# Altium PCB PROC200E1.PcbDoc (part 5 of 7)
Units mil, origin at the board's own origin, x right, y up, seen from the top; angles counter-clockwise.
Board outline 4163.97 x 3505.34 mil, 6 copper layers (Top Layer, GND1, SIG1, PWR, GND2, Bottom), stack 58.132 mil thick; 367 components, 387 nets, 1784 pads, 858 vias.
Unrouted connection lines stored in the file: 17.
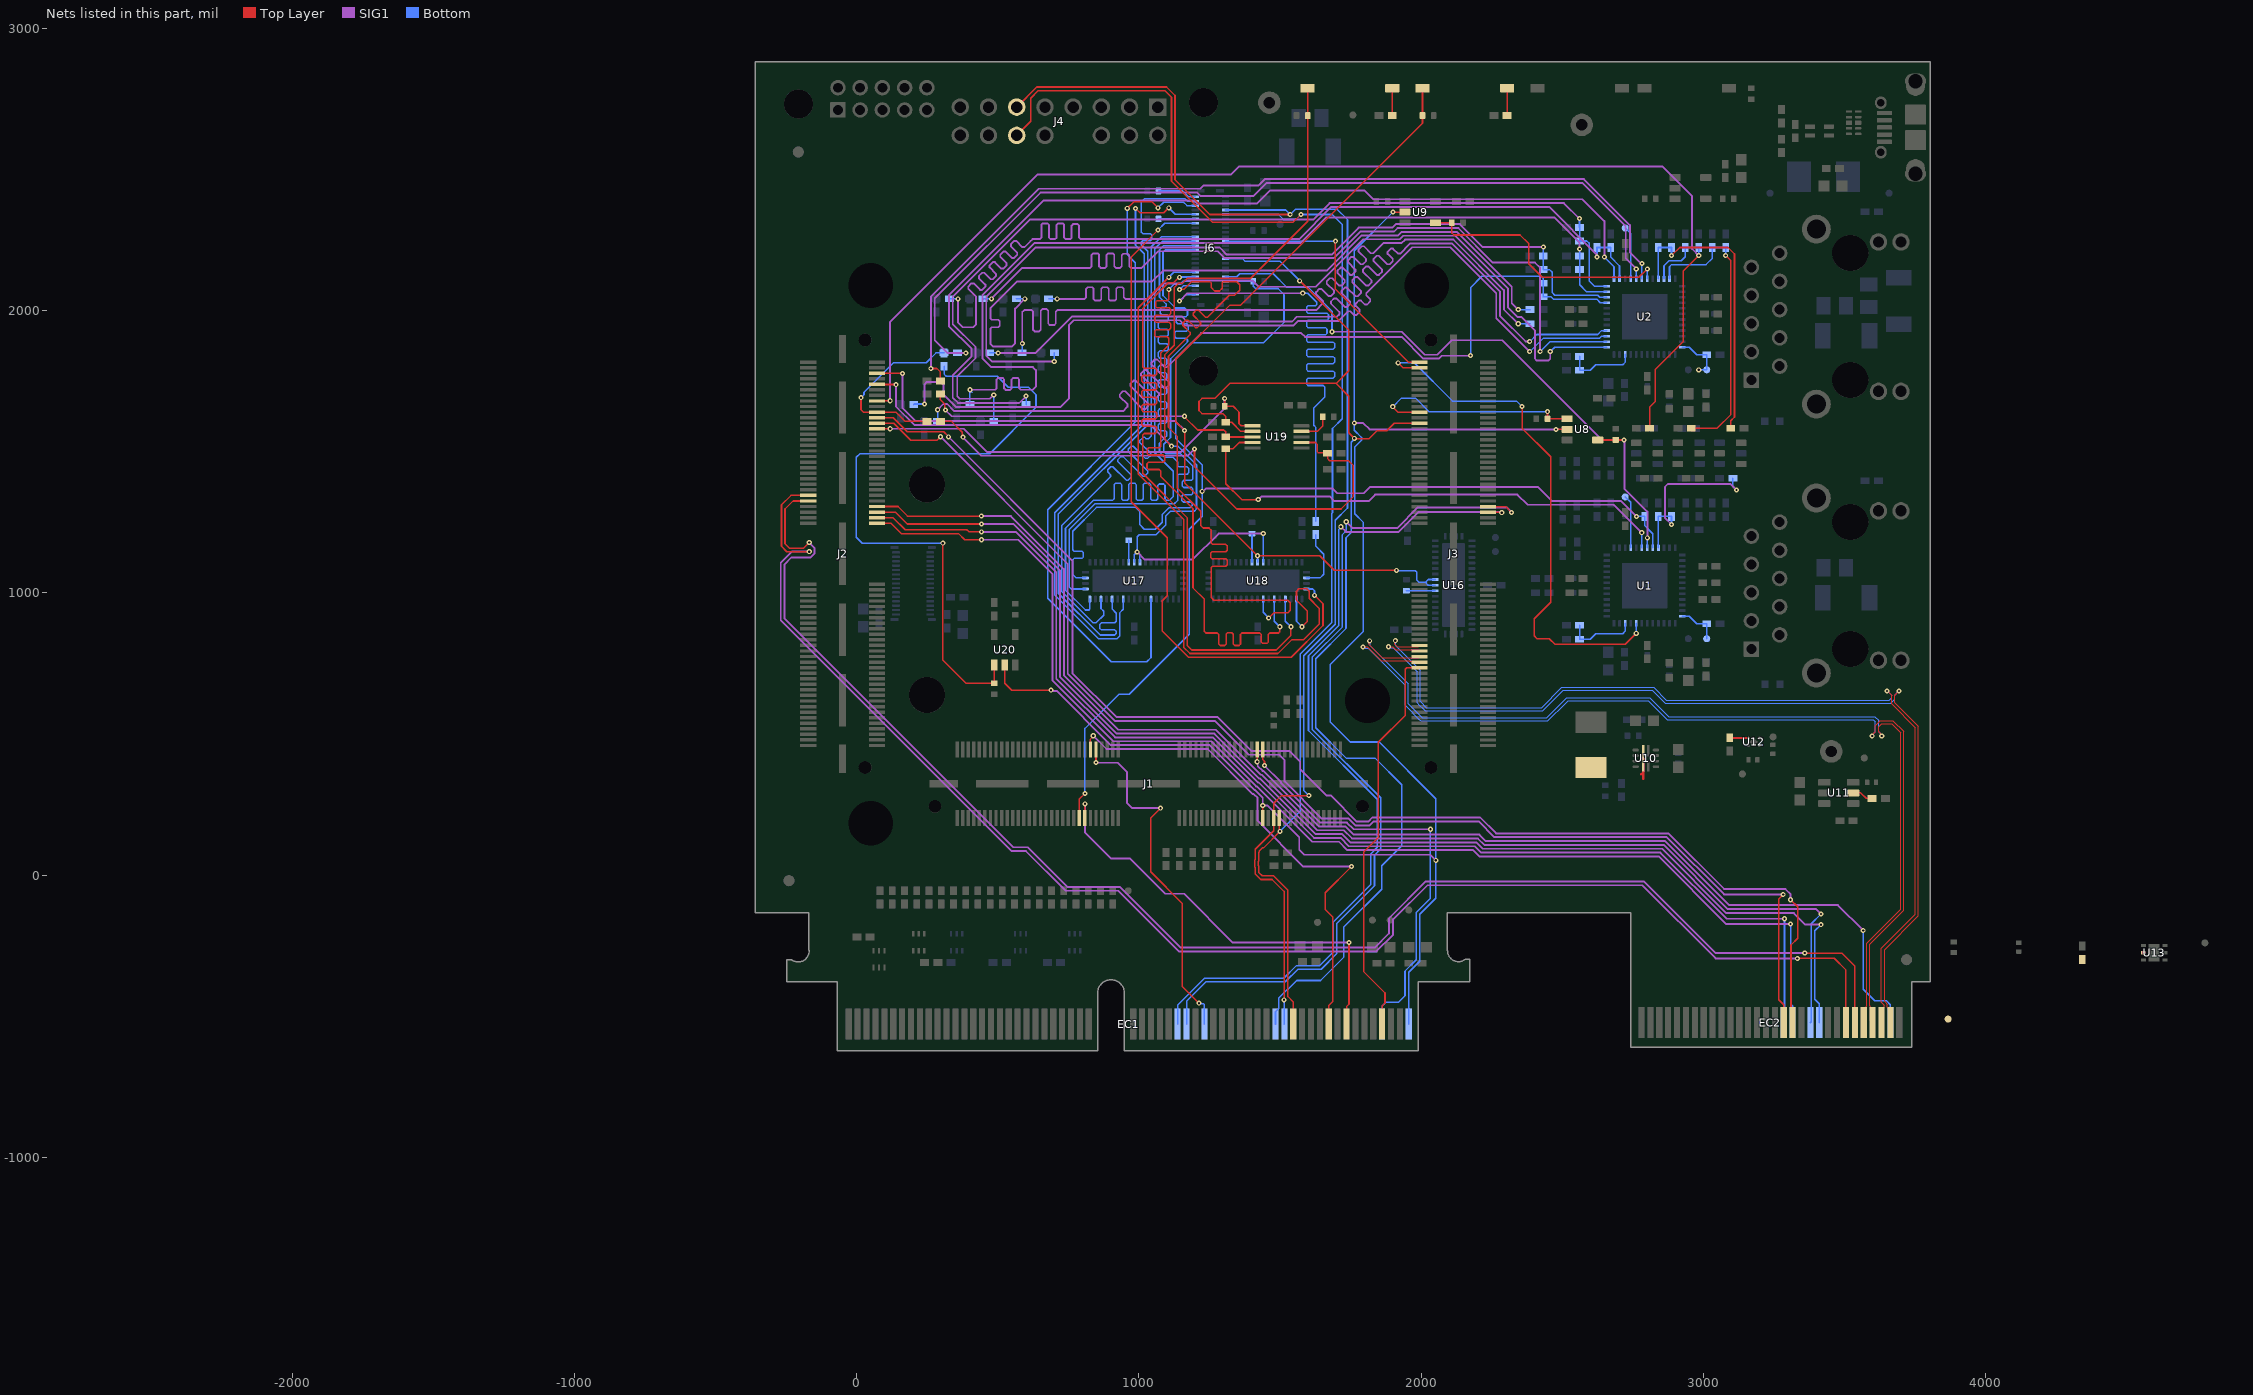
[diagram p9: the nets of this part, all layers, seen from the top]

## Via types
v1: diameter 18, hole 8, Top Layer to Bottom, tented both sides, 729 vias
v2: diameter 19.68, hole 7.87, Top Layer to Bottom, 77 vias
v3: diameter 24, hole 12, Top Layer to Bottom, tented both sides, 52 vias

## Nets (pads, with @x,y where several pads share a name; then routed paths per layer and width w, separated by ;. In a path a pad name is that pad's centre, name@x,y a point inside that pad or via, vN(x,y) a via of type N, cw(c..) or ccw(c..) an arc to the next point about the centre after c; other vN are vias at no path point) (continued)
ICSSM_MII1_RXD0: J6.23 U17.41 | length 2290.4
  Bottom w5.66: U17.41@810.53,1052.88 777.47,1052.88 765.17,1065.18 765.17,1088.34 765.17,1116.83 770.3,1121.96 798.11,1121.96 803.24,1127.1 803.24,1142.49 798.11,1147.62 770.3,1147.62 765.17,1152.76 765.17,1161.3 765.17,1218.03 849.72,1302.59 988.7,1302.59 1002.48,1288.81 1002.48,1241.75 1019.22,1225.01 1057.52,1225.01 1082.58,1250.06 1082.58,1277.88 1106.27,1301.56 1181,1301.56 1186.17,1306.73 1189,1309.57 1189,1316.82 1183.87,1321.95 1156.42,1321.95 1151.29,1327.09 1151.29,1342.48 1156.42,1347.61 1186.21,1347.61 1191.34,1352.75 1191.34,1368.14 1186.21,1373.27 1159.24,1373.27 1154.1,1378.41 1154.1,1393.8 1159.24,1398.93 1186.21,1398.93 1191.34,1404.07 1191.34,1414.21 1191.34,1448.76 1147.1,1493 1097,1493 1088.06,1501.94 1088.06,1526.51 1112,1550.45 1112,1828.89 1172.08,1888.97 1172.08,1893.89 1172.08,1896.72 1166.94,1901.85 1132.55,1901.85 1127.42,1906.99 1127.42,1922.38 1132.55,1927.51 1169.03,1927.51 1174.16,1932.65 1174.16,1948.04 1169.03,1953.17 1137.82,1953.17 1132.69,1958.31 1132.69,1973.7 1137.82,1978.83 1166.94,1978.83 1172.08,1983.97 1172.08,1999.34 1162.27,2009.15 1129.61,2009.15 1085.39,2053.38 1085.39,2206.34 1093.71,2214.65 J6.23@1199.93,2214.65
ICSSM_MII1_RXD1: J6.25 U17.39 | length 2290.4
  Bottom w5.66: U17.39@810.53,1013.51 760.06,1013.51 752.51,1021.06 752.51,1223.28 844.48,1315.25 1125.25,1315.25 1137,1327 1137,1386.93 1137,1415.42 1142.13,1420.55 1170.85,1420.55 1175.98,1425.69 1175.98,1441.08 1170.85,1446.21 1142.13,1446.21 1137,1451.35 1137,1464.34 1130.59,1470.75 1121,1480.34 1091.76,1480.34 1073,1499.1 1073,1530.49 1098,1555.49 1098,1566.93 1098,1569.76 1092.87,1574.89 1074.24,1574.89 1069.1,1580.02 1069.1,1595.42 1074.24,1600.55 1094.21,1600.55 1099.34,1605.68 1099.34,1621.08 1094.21,1626.21 1074.24,1626.21 1069.1,1631.34 1069.1,1646.74 1074.24,1651.87 1094.21,1651.87 1099.34,1657 1099.34,1672.4 1094.21,1677.53 1074.24,1677.53 1069.1,1682.66 1069.1,1698.06 1074.24,1703.19 1094.21,1703.19 1099.34,1708.32 1099.34,1723.72 1094.21,1728.85 1074.24,1728.85 1069.1,1733.98 1069.1,1749.38 1074.24,1754.51 1094.21,1754.51 1099.34,1759.64 1099.34,1775.04 1094.21,1780.17 1074.24,1780.17 1069.1,1785.3 1069.1,1800.7 1074.24,1805.83 1094.21,1805.83 1099.34,1810.96 1099.34,1826.36 1094.21,1831.49 1074.24,1831.49 1069.1,1836.62 1069.1,1852.02 1074.24,1857.15 1099.03,1857.15 1104.16,1862.28 1104.16,1877.68 1099.03,1882.81 1074.24,1882.81 1069.1,1887.94 1069.1,1903.34 1074.24,1908.47 1099.03,1908.47 1104.16,1913.6 1104.16,1929 1099.03,1934.13 1074.24,1934.13 1069.1,1939.26 1069.1,1954.66 1074.24,1959.79 1099.03,1959.79 1104.16,1964.92 1104.16,1980.32 1099.03,1985.45 1080.39,1985.45 1075.26,1990.58 1075.26,2005.98 1080.39,2011.11 1091.1,2011.11 1096.23,2016.24 1096.23,2023.5 1072.73,2047 1072.73,2059.61 1072.73,2215.26 1087.88,2230.4 J6.25@1199.93,2230.4
ICSSM_MII1_RXD2: J6.27 U17.38 | length 2290.4
  Bottom w5.66: U17.38@826.28,978.08 826.28,942.42 822.97,939.1 810.37,939.1 739.85,1009.62 739.85,1228.52 839.93,1328.6 904.94,1328.6 907.78,1328.6 912.91,1333.74 912.91,1383.55 918.04,1388.69 933.44,1388.69 938.57,1383.55 938.57,1333.04 943.7,1327.91 959.1,1327.91 964.23,1333.04 964.23,1383.55 969.36,1388.69 984.76,1388.69 989.89,1383.55 989.89,1333.04 995.02,1327.91 1010.42,1327.91 1015.55,1333.04 1015.55,1383.55 1020.68,1388.69 1036.08,1388.69 1041.21,1383.55 1041.21,1333.04 1046.34,1327.91 1061.74,1327.91 1066.87,1333.04 1066.87,1380.3 1072,1385.43 1087.4,1385.43 1092.53,1380.3 1092.53,1333.74 1097.66,1328.6 1109.14,1328.6 1109.6,1328.6 1122,1341 1122,1430.61 1056.44,1496.16 1056.44,2218.93 1083.67,2246.15 J6.27@1199.93,2246.15
ICSSM_MII1_RXD3: J6.29 U17.36 | length 2290.4
  Bottom w5.66: U17.36@865.65,978.08 865.65,944.59 875.04,935.19 875.04,920.48 849.08,894.52 836.59,894.52 727.19,1003.91 727.19,1239.31 897.3,1409.42 899.3,1411.42 899.3,1418.68 889.36,1428.63 889.36,1435.89 900.24,1446.77 907.5,1446.77 954.89,1399.38 962.15,1399.38 973.04,1410.27 973.04,1417.52 925.65,1464.92 925.65,1472.17 936.53,1483.06 943.79,1483.06 1013.25,1413.6 1020.51,1413.6 1031.4,1424.49 1031.4,1431.74 961.93,1501.21 961.93,1508.46 972.82,1519.35 980.08,1519.35 1023.26,1476.17 1030.52,1476.17 1041.4,1487.06 1041.4,1494.32 1003.16,1532.56 1003.16,1539.81 1014.05,1550.7 1021.31,1550.7 1026.31,1545.69 1033.57,1545.69 1038.39,1550.51 1043.78,1555.9 1043.78,2225.87 1079.81,2261.9 J6.29@1199.93,2261.9
ICSSM_MII1_RXDV: J6.45 U17.34 | length 2290.4
  Bottom w5.66: U17.34@905.02,978.08 905.02,942.53 919.71,927.85 919.86,927.69 919.86,899.35 914.73,894.22 866.99,894.22 861.86,889.09 861.86,873.69 866.99,868.56 914.73,868.56 919.86,863.43 919.86,856.56 919.86,856.37 913.92,850.42 862.59,850.42 714.53,998.48 714.53,1278.96 1031.12,1595.56 1031.12,2210.31 1022.78,2218.65 1008.54,2232.89 1008.54,2242.01 1013.67,2247.14 1040.45,2247.14 1045.58,2252.28 1045.58,2267.67 1040.45,2272.8 1013.67,2272.8 1008.54,2277.94 1008.54,2299.53 1008.54,2385.86 1019.34,2396.66 1163.43,2396.66 1172.2,2387.88 J6.45@1199.93,2387.88
ICSSM_MII1_RXER: J6.39 U17.32 | length 2182.8
  Top Layer w5.66: v1(988,2362) 1003.57,2346.43 1088.06,2346.43 v1(1105.89,2364.26)
  Bottom w5.66: U17.32@944.39,978.08 944.39,941.96 932.57,930.13 932.57,848.03 922.28,837.75 856.58,837.75 701.87,992.46 701.87,1284.21 1018.46,1600.8 1018.46,2201.25 988,2231.71 v1(988,2362) ; v1(1105.89,2364.26) 1128.6,2341.56 1199.01,2341.56 J6.39@1199.93,2340.64
ICSSM_MII1_RXLINK: J6.43 U17.27 | length 2467.7
  Top Layer w5.66: v1(958.67,2362.28) 981.39,2385.01 1047.15,2385.01 v1(1067.89,2364.26)
  Bottom w5.66: v1(958.67,2362.28) 958.67,2198.44 987.34,2169.76 987.34,1605.48 676.55,1294.69 676.55,980.56 901.55,755.56 1027.51,755.56 1042.82,770.87 U17.27@1042.82,978.08 ; v1(1067.89,2364.26) 1087.63,2384 1158.18,2384 1170.05,2372.14 J6.43@1199.93,2372.14
ICSSM_MII1_TXCLK: J6.3 R153.2 | length 2294.8
  SIG1 w6.66: v1(1143.89,2033.94) 1171.62,2061.66 v1(1580.57,2061.66)
  Bottom w5.66: v1(1143.89,2033.94) 1167.13,2057.17 J6.3@1199.93,2057.17 ; v1(1580.57,2061.66) 1597.74,2061.66 1614.19,2045.22 1630.29,2029.11 1630.29,2021.86 1625.16,2016.72 1599.14,2016.72 1594.01,2011.59 1594.01,1996.2 1599.14,1991.06 1666.38,1991.06 1671.51,1985.93 1671.51,1970.54 1666.38,1965.4 1599.14,1965.4 1594.01,1960.27 1594.01,1944.88 1599.14,1939.74 1661.21,1939.74 1666.34,1934.61 1666.34,1919.22 1661.21,1914.08 1599.14,1914.08 1594.01,1908.95 1594.01,1893.56 1599.14,1888.42 1688.02,1888.42 1693.15,1883.29 1693.15,1867.9 1688.02,1862.76 1599.14,1862.76 1594.01,1857.63 1594.01,1842.24 1599.14,1837.1 1688.02,1837.1 1693.15,1831.97 1693.15,1816.58 1688.02,1811.44 1599.14,1811.44 1594.01,1806.31 1594.01,1790.92 1599.14,1785.78 1688.02,1785.78 1693.15,1780.65 1693.15,1765.26 1688.02,1760.12 1599.14,1760.12 1594.01,1754.99 1594.01,1739.6 1599.14,1734.46 1653.03,1734.46 1658.16,1729.33 1658.16,1709.94 1658.16,1693.71 1619.42,1654.97 1619.42,1593.67 1627.09,1586 R153.2@1627.09,1253.39
ICSSM_MII1_TXD0: J6.7 U18.29 | length 2485.3
  Top Layer w5.66: v1(1143.89,2074.96) 1159.09,2074.96 1186.44,2102.31 1252.13,2102.31 1256.76,2097.69 1256.76,2080.76 1267.98,2069.54 1285.54,2069.54 1294.95,2078.95 1294.95,2098.8 1298.27,2102.12 1346.77,2102.12 1356.96,2091.93 1356.96,2072.29 1338.76,2054.09 1320.09,2054.09 1293.76,2027.76 1242.82,1976.82 1235.56,1976.82 1210.63,2001.76 1203.37,2001.76 1192.48,1990.87 1192.48,1983.62 1218.2,1957.9 1218.2,1950.64 1207.31,1939.76 1200.05,1939.76 1173.63,1966.18 1166.38,1966.18 1155.49,1955.29 1155.49,1948.03 1181.13,1922.39 1181.13,1915.13 1179.13,1913.13 1104.72,1838.72 1104.72,1585.98 1135.28,1555.42 1135.28,1372.18 1218.71,1288.74 1218.71,1238.44 1227.38,1229.77 1248.31,1229.77 1255.87,1222.21 1255.87,1193.21 1255.87,1176.73 1261,1171.6 1307.59,1171.6 1312.73,1166.47 1312.73,1151.07 1307.59,1145.94 1259.22,1145.94 1254.09,1140.81 1254.09,1125.41 1259.22,1120.28 1307.59,1120.28 1312.73,1115.15 1312.73,1099.75 1307.59,1094.62 1261,1094.62 1255.87,1089.49 1255.87,1061 1255.87,983.29 1265.16,974 1527.4,974 1536.33,965.08 1536.33,937.92 1528.15,929.74 1478.62,929.74 v1(1459.8,910.92)
  Bottom w5.66: v1(1143.89,2074.96) 1144.7,2074.96 1158.4,2088.67 J6.7@1199.93,2088.67 ; U18.29@1440.11,978.08 1440.11,930.72 1459.8,911.04 v1(1459.8,910.92)
ICSSM_MII1_TXD1: J6.9 U18.27 | length 2484
  Top Layer w5.66: v1(1105.89,2074.96) 1105.89,2059.27 1105.89,2040.39 1100.76,2035.26 1064.01,2035.26 1058.88,2030.13 1058.88,2014.73 1064.01,2009.6 1107.02,2009.6 1112.15,2004.47 1112.15,1989.07 1107.02,1983.94 1061.03,1983.94 1055.89,1978.81 1055.89,1963.41 1061.03,1958.28 1107.02,1958.28 1112.15,1953.15 1112.15,1937.75 1107.02,1932.62 1061.03,1932.62 1055.89,1927.49 1055.89,1912.09 1061.03,1906.96 1100.76,1906.96 1105.89,1901.83 1105.89,1899 1105.89,1878.28 1077.62,1850.01 1077.62,1553.31 1077.62,1519.2 1072.49,1514.07 1034.85,1514.07 1029.72,1508.94 1029.72,1493.54 1034.85,1488.41 1086.21,1488.41 1091.34,1483.28 1091.34,1467.88 1086.21,1462.75 1033.84,1462.75 1028.71,1457.62 1028.71,1442.22 1033.84,1437.09 1072.49,1437.09 1077.62,1431.96 1077.62,1429.13 1077.62,1411.89 1191.74,1297.77 1191.74,1017.34 1231.27,977.81 1231.27,863.63 1237.33,857.57 1249.44,857.57 1277.93,857.57 1283.06,852.44 1283.06,818.64 1288.2,813.51 1303.59,813.51 1308.72,818.64 1308.72,853.38 1313.86,858.51 1329.25,858.51 1334.38,853.38 1334.38,818.64 1339.52,813.51 1354.91,813.51 1360.04,818.64 1360.04,852.44 1365.18,857.57 1384,857.57 1399.52,857.57 1428.01,857.57 1433.14,852.44 1433.14,825.8 1438.27,820.66 1453.67,820.66 1458.8,825.8 1458.8,852.44 1463.93,857.57 1494,857.57 1494.76,857.57 1499.17,861.98 v1(1499.17,879.94)
  Bottom w5.66: v1@1105.89,2077.96 1108.89,2077.96 1123.72,2092.79 1144.5,2092.79 1156.13,2104.42 J6.9@1199.93,2104.42 ; U18.27@1479.48,978.08 1479.48,899.62 v1(1499.17,879.94)
ICSSM_MII1_TXD2: J6.11 U18.25 | length 2485.7
  Top Layer w5.66: v1(1143.89,2117.99) 1142.11,2117.99 1122.4,2098.27 1103.99,2098.27 1013.3,2007.59 1013.3,1890 1013.3,1800.69 1018.43,1795.56 1057.39,1795.56 1062.52,1790.43 1062.52,1775.03 1057.39,1769.9 1015.61,1769.9 1010.48,1764.77 1010.48,1749.37 1015.61,1744.24 1058.17,1744.24 1063.3,1739.11 1063.3,1723.71 1058.17,1718.58 1015.61,1718.58 1010.48,1713.45 1010.48,1698.05 1015.61,1692.92 1058.17,1692.92 1063.3,1687.79 1063.3,1672.39 1058.17,1667.26 1015.61,1667.26 1010.48,1662.13 1010.48,1646.73 1015.61,1641.6 1058.17,1641.6 1063.3,1636.47 1063.3,1621.07 1058.17,1615.94 1015.61,1615.94 1010.48,1610.81 1010.48,1595.41 1015.61,1590.28 1058.17,1590.28 1063.3,1585.15 1063.3,1569.75 1058.17,1564.62 1018.43,1564.62 1013.3,1559.49 1013.3,1531 1013.3,1423.47 1171.73,1265.04 1171.73,812.87 1187.04,797.56 1486.21,797.56 1538.54,849.88 v1(1538.54,879.94)
  Bottom w5.66: v1(1143.89,2117.99) 1144.98,2119.08 1198.84,2119.08 J6.11@1199.93,2120.17 ; U18.25@1518.85,978.08 1518.85,899.62 v1(1538.54,879.94)
ICSSM_MII1_TXD3: J6.13 U18.23 | length 2493.9
  Top Layer w5.66: v1(1105.89,2117.99) 1105.8,2117.99 997.82,2010.01 997.82,1421.05 1159.07,1259.8 1159.07,806.64 1180.81,784.9 1492.52,784.9 1541.99,834.37 1584.23,834.37 1638.27,888.41 1638.27,945.57 1603.2,980.64 1603.2,1005.25 1594.37,1014.07 1566.7,1014.07 1558.17,1005.54 1558.17,974.05 1595.74,936.48 1595.74,897.77 v1(1577.91,879.94)
  Bottom w5.66: v1(1105.89,2117.99) 1123.82,2135.91 J6.13@1199.93,2135.91 ; U18.23@1558.22,978.08 1558.22,899.62 v1(1577.91,879.94)
ICSSM_MII1_TXEN: J6.35 U18.21 | length 2483.3
  Top Layer w5.66: v1(1067.89,2285.52) 972.5,2190.13 972.5,1322.49 1100.23,1194.76 1100.23,989.34 1082.9,972 1082.9,864.49 1175.77,771.63 1539.38,771.63 1652.04,884.28 1652.04,960.96 v1(1622,991)
  Bottom w5.66: v1(1067.89,2285.52) 1091.52,2309.14 J6.35@1199.93,2309.14 ; U18.21@1593.65,1013.51 1616.09,1013.51 1622,1007.6 v1(1622,991)
JTAG_TDO/ETH1_GPIO_1: R67.1 R76.2 U2.22 | length 250
  Bottom w5.66: R67.1@2561.67,1837.3 R76.2@2561.67,1788.19 2599.38,1788.19 2618.87,1807.69 2713.98,1807.69 2722.59,1816.3 U2.22@2722.59,1844.65
JTAG_TDO/PHY2_GPIO_1: R14.1 R23.2 U1.22 | length 250
  Bottom w5.66: R14.1@2561.67,884.54 R23.2@2561.67,835.44 2599.38,835.44 2618.87,854.93 2713.98,854.93 2722.59,863.54 U1.22@2722.59,891.89
LED2_2: R10.1 R19.2 R120.1 U1.45 | length 644.4
  SIG1 w6.66: v1(2887.03,1242.08) 2863.46,1265.64 2863.46,1374.96 2874.6,1386.1 3095.34,1386.1 v1(3116.99,1364.44)
  Bottom w5.66: U1.45@2840.7,1159.61 2840.7,1269.61 R10.1@2839.49,1270.82 R19.2@2887.03,1270.82 v1(2887.03,1242.08) ; R120.1@3104.35,1405.81 3104.35,1377.9 3116.99,1365.25 v1(3116.99,1364.44)
LED_0: R64.1 R73.2 R109.1 U2.47 | length 1053.1
  Top Layer w5.66: R109.1@2956.9,1582.81 3048.18,1582.81 3097.49,1632.13 3097.49,2176.37 v1(3079.03,2194.83)
  Bottom w5.66: U2.47@2880.07,2112.37 2880.07,2155.7 2887.35,2162.98 3009.25,2162.98 3031.24,2184.96 R64.1@3031.24,2223.58 R73.2@3079.03,2223.58 v1(3079.03,2194.83)
LED_2: R65.1 R74.2 R113.1 U2.45 | length 1056
  Top Layer w5.66: v1(2887.03,2194.83) 2915.78,2223.58 3087.42,2223.58 3110.15,2200.85 3110.15,1622.76 3096.87,1609.47 R113.1@3096.87,1582.81
  Bottom w5.66: U2.45@2840.7,2112.37 2840.7,2222.37 R65.1@2839.49,2223.58 R74.2@2887.03,2223.58 v1(2887.03,2194.83)
MCU_GPIO63: EC2.167 J2.50 | length 5382.8
  Top Layer w5.66: J2.50@-171.52,1345.08 -233.15,1345.08 -266.55,1311.68 -266.55,1164.9 -247.65,1146 v1(-168,1146) ; v1(3332.7,-295.23) 3463.62,-295.23 3505.04,-336.65 EC2.167@3505.04,-522.97
  SIG1 w6.66: v1(-168,1146) -229.63,1146 -269.04,1106.59 -269.04,903.01 548.94,85.03 599.9,85.03 740.67,-55.75 926.74,-55.75 1141.79,-270.79 1841.41,-270.79 1899.69,-212.5 1899.69,-158.78 2022.47,-36 2783.84,-36 3043.07,-295.23 v1(3332.7,-295.23)
MCU_GPIO64: EC2.169 J2.52 | length 5406.8
  Top Layer w5.66: J2.52@-171.52,1325.39 -225.37,1325.39 -253.89,1296.87 -253.89,1173.42 -239.13,1158.66 -187.34,1158.66 v1(-168,1178) ; v1(3359,-276.43) 3490.68,-276.43 3536.54,-322.29 EC2.169@3536.54,-522.97
  SIG1 w6.66: v1(-168,1178) -149.67,1159.67 -149.67,1138.41 -162.75,1125.33 -230.98,1125.33 -255.38,1100.93 -255.38,908.67 554.6,98.69 605.56,98.69 746.33,-42.09 932.4,-42.09 1147.44,-257.13 1835.75,-257.13 1886.03,-206.85 1886.03,-153.13 2016.82,-22.34 2789.5,-22.34 3043.59,-276.43 v1(3359,-276.43)
MCU_GPIO67: EC2.154 J2.57 | length 4394.3
  Top Layer w5.66: J2.57@71.48,1266.34 128.95,1266.34 171.67,1223.62 389.91,1223.62 397.56,1215.97 v1(442,1215.97)
  SIG1 w6.66: v1(442,1215.97) 563.87,1215.97 707.02,1072.82 707.02,696.03 915.39,487.66 1261.46,487.66 1421,328.12 1423.66,328.12 1620.29,131.48 1714.53,131.48 1743.77,102.24 2189.5,102.24 2212.15,79.59 2847.73,79.59 3082.21,-154.9 v1(3287.21,-154.9)
  Bottom w5.66: EC2.154@3284.57,-522.97 3287.21,-520.32 v1(3287.21,-154.9)
MCU_GPIO68: EC2.156 J2.59 | length 4398.7
  Top Layer w5.66: J2.59@71.48,1246.65 121.33,1246.65 157.98,1210 360.93,1210 382.95,1187.97 v1(442,1187.97)
  SIG1 w6.66: v1(442,1187.97) 572.55,1187.97 693.36,1067.16 693.36,690.37 909.73,474 1255.8,474 1415.34,314.46 1418,314.46 1614.64,117.82 1708.87,117.82 1738.11,88.58 2183.84,88.58 2206.49,65.93 2842.07,65.93 3081.77,-173.77 v1(3308.99,-173.77)
  Bottom w5.66: v1(3308.99,-173.77) 3308.99,-455.33 3316.06,-462.4 EC2.156@3316.06,-522.97
MCU_GPIO69: EC2.160 J2.53 | length 4564.5
  Top Layer w5.66: J2.53@71.48,1305.71 146.36,1305.71 180.1,1271.97 v1(441.73,1271.97)
  SIG1 w6.66: v1(441.73,1271.97) 546.51,1271.97 734.34,1084.14 734.34,707.34 926.7,514.98 1272.77,514.98 1432.31,355.44 1434.97,355.44 1631.61,158.8 1725.85,158.8 1755.09,129.56 2200.81,129.56 2223.46,106.91 2859.04,106.91 3086.32,-120.36 3399.03,-120.36 v1(3416.74,-138.07)
  Bottom w5.66: EC2.160@3379.06,-522.97 3382.04,-519.99 3382.04,-172.78 v1(3416.74,-138.07)
MCU_GPIO70: EC2.162 J2.55 | length 4534.4
  Top Layer w5.66: J2.55@71.48,1286.02 136.98,1286.02 179.03,1243.97 v1(442,1243.97)
  SIG1 w6.66: v1(442,1243.97) 555.19,1243.97 720.68,1078.48 720.68,701.68 921.05,501.32 1267.11,501.32 1426.65,341.78 1429.32,341.78 1625.95,145.14 1720.19,145.14 1749.43,115.9 2195.15,115.9 2217.8,93.25 2853.39,93.25 3081.59,-134.95 3320.95,-134.95 3361.67,-175.67 v1(3416.74,-175.67)
  Bottom w5.66: EC2.162@3410.55,-522.97 3410.55,-455.55 3394.7,-439.69 3394.7,-197.72 v1(3416.74,-175.67)
MCU_GPIO74: J2.25 R106.1 U19.1 | length 1544.9
  Top Layer w5.66: v1(1303.76,1688.13) 1303.65,1688.02 1303.65,1661.12 R106.1@1303.53,1661 1334.09,1661 1354.68,1640.42 1354.68,1599.32 1362.35,1591.65 U19.1@1402.41,1591.65
  Top Layer w6.66: J2.25@71.48,1581.3 v1(118.61,1581.3)
  SIG1 w6.66: v1(118.61,1581.3) 379.55,1581.3 461.32,1499.53 1149.6,1499.53 1300.41,1650.33 1303.12,1650.33 1303.76,1650.97 v1(1303.76,1688.13)
MCU_GPIO120: EC1.70 J3.68 | length 3154.8
  Top Layer w5.66: J3.68@2236.48,1305.51 2299.65,1305.51 v1(2320.41,1284.76)
  SIG1 w6.66: v1(1734.52,1251.75) 1756.98,1229.3 1914.64,1229.3 1987.75,1302.41 2302.75,1302.41 v1(2320.41,1284.76)
  Bottom w5.66: EC1.70@1168.76,-528.32 1168.76,-446.76 1237.24,-378.28 1518.43,-378.28 1563.32,-333.39 1645.61,-333.39 1701,-278 1701,-171.85 1834.61,-38.24 1834.61,70.59 1856.95,92.93 1856.95,273.58 1613.47,517.06 1613.47,771.53 1721,879.06 1721,1206.48 1735.01,1220.49 1735.01,1251.27 v1(1734.52,1251.75)
MCU_GPIO121: EC1.74 J1.70 | length 1273.7
  Top Layer w5.66: v1(847.73,398.41) 847.85,398.53 847.85,444.76 J1.70@847.97,444.88 ; v1(1076.58,237.09) v1(1076.58,237.09) 1041.55,201.97 1041.55,11.52 1153.78,-100.72 1153.78,-394.78 v1(1212.89,-453.88)
  SIG1 w6.66: v1(847.73,398.41) 848.13,398 925,398 958,365 958,255 976,237 1076.49,237 v1(1076.58,237.09)
  Bottom w5.66: v1(1212.89,-453.88) 1214.3,-455.29 1228.44,-455.29 1231.75,-458.61 EC1.74@1231.75,-528.32
MCU_GPIO124: EC1.101 J1.72 | length 1820.9
  Top Layer w5.66: J1.72@828.29,444.88 828.14,445.03 828.14,481.92 838.1,491.87 v1(838.1,493.68) ; EC1.101@1672.7,-528.32 1672.7,-461.89 1686.94,-447.65 1686.94,-148.41 1660.6,-122.07 1660.6,-62.46 v1(1753.03,29.98)
  SIG1 w6.66: v1(838.1,493.68) 885.11,446.68 1244.48,446.68 1404.02,287.14 1406.68,287.14 1420.38,273.44 1420.38,192.33 1582.73,29.98 v1(1753.03,29.98)
MCU_GPIO126: EC1.105 J1.73 | length 1541.7
  Top Layer w5.66: J1.73@808.6,201.89 v1(808.6,252.36) ; EC1.105@1735.69,-528.32 1735.69,-465.72 1744.15,-457.26 v1(1744.15,-238.8)
  SIG1 w6.66: v1(808.6,252.36) 808.6,151.6 900.87,59.33 968.09,59.33 1093.79,-66.37 1160.56,-66.37 1333.19,-239 1743.96,-239 v1(1744.15,-238.8)
MCU_GPIO136: EC2.153 J2.23 | length 4665
  Top Layer w5.66: J2.23@71.48,1600.98 131.47,1600.98 191.45,1541 284.42,1541 296.43,1553 v1(297.16,1553) ; v1(3282.68,-68.6) 3266.74,-84.54 3266.74,-441.74 3284.57,-459.57 EC2.153@3284.57,-522.97
  SIG1 w6.66: v1(297.16,1553) 748,1102.16 748,713 915.29,545.71 1270.17,545.71 1389.51,426.37 1497.28,426.37 1516.45,407.2 1516.45,331.92 1648.59,199.78 1742.82,199.78 1766.62,175.99 1817.94,175.99 1832.29,190.33 2203.49,190.33 2259.59,134.23 2870.36,134.23 3073.19,-68.6 v1(3282.68,-68.6)
MCU_GPIO137: EC2.155 J2.21 | length 4675.2
  Top Layer w5.66: J2.21@71.48,1620.67 129.69,1620.67 179.53,1570.83 308.15,1570.83 325.23,1553.76 v1(325.23,1552.69) ; v1(3308.99,-87.4) 3334.14,-112.55 3334.14,-223.9 3310.42,-247.63 3310.42,-517.32 EC2.155@3316.06,-522.97
  SIG1 w6.66: v1(325.23,1552.69) 764.56,1113.36 764.56,715.76 920.65,559.67 1278.65,559.67 1373.54,464.78 1398.29,440.03 1532.95,440.03 1571.78,401.2 1571.78,375.22 1665.66,281.34 1680.58,281.34 1772.27,189.65 1812.29,189.65 1826.63,203.99 2209.15,203.99 2265.25,147.89 2876.02,147.89 3073.3,-49.39 3290.48,-49.39 3308.99,-67.9 v1(3308.99,-87.4)
MCU_I2C0_SCL: EC1.93 J1.23 J4.12 J6.40 | length 5023.2
  Top Layer w5.66: J4.12@566.91,2620.91 616.46,2670.47 616.46,2752.46 643.48,2779.48 1091.86,2779.48 1115.31,2756.03 1115.31,2458.64 1260.23,2313.72 1547.08,2313.72 v1(1574,2340.64) ; v1@1497.58,155.04 J1.23@1497.58,201.89 ; v1(1499.97,155.04) 1441.03,96.1 1437.2,96.1 1426.75,85.65 1426.75,81.82 1424.77,79.84 1424.77,49.99 1423.17,48.39 1423.17,33.61 1424.77,32.01 1424.77,9.15 1436.82,-2.9 1476.83,-2.9 1527.88,-53.95 1527.88,-430.54 1546.72,-449.37 EC1.93@1546.72,-528.32
  Bottom w5.66: J6.40@1306.63,2340.64 1494.53,2340.64 1512.36,2322.81 1556.17,2322.81 v1(1574,2340.64) 1685.33,2340.64 1720.84,2305.13 1720.84,1617.23 1685.94,1582.32 1685.94,1284.76 1682.58,1281.4 1682.58,894.35 1570.89,782.66 1570.89,225.96 v1(1499.97,155.04)
MCU_I2C0_SDA: EC1.92 J1.25 J4.11 J6.42 | length 4947
  Top Layer w5.66: J4.11@566.91,2720.91 638.14,2792.14 1097.86,2792.14 1127.97,2762.03 1127.97,2463.89 1251.22,2340.64 v1(1536,2340.64) ; v1(1514.21,-442.09) 1514.21,-58.19 1471.58,-15.56 1431.58,-15.56 1412.11,3.91 1412.11,26.77 1410.51,28.37 1410.51,53.63 1412.11,55.23 1412.11,91.05 1477.89,156.83 J1.25@1477.89,201.89 1477.89,254.01 1505.4,281.52 v1(1602.01,281.52)
  Bottom w5.66: J6.42@1306.63,2356.39 1520.25,2356.39 v1(1536,2340.64) 1553.83,2358.47 1703.04,2358.47 1739,2322.51 1739,1300.65 1695.24,1256.89 1695.24,889.1 1583.55,777.42 1583.55,299.98 v1(1602.01,281.52) ; v1(1514.21,-442.09) 1514.21,-527.32 EC1.92@1515.22,-528.32
MCU_PORz: EC1.120 J1.29 TP25.1 U8.2 U9.2 U20.2 | length 6012.4
  Top Layer w5.66: U20.2@524.89,744.39 524.89,679.94 549.83,655 v1(688.6,655) ; J1.29@1438.52,201.89 1438.62,201.98 1438.62,246.54 v1(1438.71,246.63) ; v1(1900,2349) 1942.15,2349 U9.2@1942.3,2349.15 ; v1(2478,1579) U8.2@2517.32,1579
  SIG1 w6.66: v1(688.6,655) 690.77,652.83 708.44,652.83 900.93,460.34 1250.14,460.34 1409.68,300.8 1412.34,300.8 1438.71,274.43 v1(1438.71,246.63) 1454.64,246.63 1568,133.28 1568,90 1586.06,71.94 2032.25,71.94 v1(2051.92,52.27) ; v1(1763.17,1601.67) 1794.4,1601.67 1817.07,1579 2476,1579 v1@2476.04,1579.04
  Bottom w5.66: v1(1900,2349) 1763.17,2212.17 v1(1763.17,1601.67) 1763.17,1575.82 1788.53,1550.47 1788.53,1540.52 1765.01,1517 1765.01,1279.85 1795.3,1249.56 1795.3,863.84 1677.42,745.96 1677.42,542.63 1748.51,471.54 1851.08,471.54 2051.92,270.71 v1(2051.92,52.27) 2051.92,-81.95 1995.29,-138.57 1995.29,-305.49 1956.16,-344.62 EC1.120@1956.16,-528.32
MDIO0_MDIO: J2.19 R55.1 R56.1 R162.2 | length 659.5
  Top Layer w5.66: v1(15.1,1691.57) 15.1,1648.91 23.66,1640.35 J2.19@71.48,1640.35 138.65,1640.35 171.75,1607.25 R162.2@249.43,1607.25
  Bottom w5.66: v1(15.1,1691.57) 25.82,1702.29 25.82,1711.07 130.4,1815.64 246.57,1815.64 281,1850.07 R56.1@309.54,1850.07
MII0/MII1_MUX2_EN: R99.2 U18.8 | length 102.1
  Bottom w5.66: U18.8@1400.74,1108 R99.2@1400.74,1210.08
MII0/MII1_RST: J6.12 R44.2 U1.43 U8.4 | length 2255.6
  Top Layer w5.66: U8.4@2625.62,1541.57 R44.2@2689.49,1541.57 v1(2718.94,1541.57)
  SIG1 w6.66: v1(1684.17,1925) 1931.92,1925 2013.38,1843.54 2056.74,1843.54 2108.2,1895 2287,1895 2640.43,1541.57 v1(2718.94,1541.57) 2721,1539.5 2721,1367.83 2801.33,1287.5 v1(2801.33,1194.93)
  Bottom w5.66: J6.12@1306.63,2120.17 1346.35,2120.17 1356.9,2130.71 1475.52,2130.71 1522.7,2083.53 1598.75,2083.53 1684.17,1998.11 v1(1684.17,1925) ; U1.43@2801.33,1159.61 v1(2801.33,1194.93)
MII0_INTn: J1.75 R5.1 U1.44 | length 4395.9
  Top Layer w5.66: J1.75@788.92,201.89 788.92,269.68 v1(808.6,289.36)
  SIG1 w6.66: v1(1224.21,1359.49) 1227.28,1359.49 1237.02,1369.24 1686.79,1369.24 1703.15,1352.88 1796.33,1352.88 1818.83,1375.38 2412.32,1375.38 2461.96,1325.74 2707.83,1325.74 v1(2762.75,1270.82)
  Bottom w5.66: v1(808.6,289.36) 808.6,519.6 929.49,640.49 965.32,640.49 1177.85,853.02 1177.85,1224.97 1224.21,1271.33 v1(1224.21,1359.49) 1224.21,1452.97 1130.04,1547.13 1130.04,1829.03 1186.69,1885.67 1441.75,1885.67 1514.12,1958.05 1514.12,2056.83 1492.81,2078.14 1413.13,2078.14 1404.77,2086.5 1404.77,2104.42 1306.63,2104.42 ; v1(2762.75,1270.82) R5.1@2791.95,1270.82 2791.95,1238.41 2821.02,1209.34 U1.44@2821.02,1159.61
MII0_MUX1_EN1: R95.2 U16.8 | length 102.1
  Bottom w5.66: R95.2@1947.94,1007.48 U16.8@2050.02,1007.48
MII0_MUX_SEL: J2.5 R97.1 SW3.1 U16.9 U16.10 U18.9 | length 4158.5
  Top Layer w5.66: J2.5@71.48,1778.15 72.1,1777.53 v1(162,1777.53) ; v1(1420.43,1131.35) 1161.75,1390.03 v1(1161.75,1575.32) 1130.62,1606.46 1130.62,1827.25 1322.82,2019.46 1360.84,2019.46 2004.72,2663.34 R97.1@2004.72,2691 SW3.1@2004.72,2788 ; v1@1420.43,1132.49 1421.56,1131.35 1640.98,1131.35 1692.48,1079.86 v1(1913.03,1079.86)
  SIG1 w6.66: v1(162,1777.53) 162,1656 209.38,1608.62 1128.45,1608.62 v1(1161.75,1575.32)
  Bottom w5.66: U18.9@1420.43,1108 v1(1420.43,1131.35) ; v1(1913.03,1079.86) 1914.63,1078.26 1979.23,1078.26 1985.03,1072.46 1985.03,1044.3 1992.17,1037.16 2017.38,1037.16 ; U16.9@2049.71,1027.17 2025.03,1027.17 2017.38,1034.82 2017.38,1039.51 2025.03,1047.16 U16.10@2049.71,1047.16
MII1_EEPROM_A0: J6.47 R82.1 | length 138
  Bottom w5.66: R82.1@1070.25,2423.63 1154.36,2423.63 1174.36,2403.63 J6.47@1199.93,2403.63
MII1_EEPROM_A2: J6.37 R83.1 | length 130.7
  Bottom w5.66: R83.1@1069.26,2324.89 J6.37@1199.93,2324.89
MII1_INTn: EC1.68 J3.66 J6.10 R79.2 | length 3073.5
  Top Layer w5.66: J3.66@2236.48,1285.83 2237.35,1284.95 2284.58,1284.95 v1(2285.46,1284.08)
  SIG1 w6.66: v1(1715.53,1234) 1733.89,1215.64 1920.3,1215.64 1990.49,1285.83 2283.71,1285.83 v1(2285.46,1284.08)
  Bottom w5.66: EC1.68@1137.27,-528.32 1137.27,-460.36 1232,-365.62 1513.18,-365.62 1558.08,-320.73 1640.37,-320.73 1688.34,-272.75 1688.34,-166.61 1821.95,-33 1821.95,75.83 1844.29,98.17 1844.29,268.34 1600.81,511.82 1600.81,776.77 1708.34,884.3 1708.34,1224.52 1715.53,1231.7 v1(1715.53,1234)
MII1_MUX3_EN: R96.2 U17.8 | length 78.1
  Bottom w5.66: U17.8@964.08,1108 R96.2@964.08,1186.15
MII1_MUX_SEL: J2.9 R98.1 SW4.1 U17.9 U17.10 U18.10 | length 4083.1
  Top Layer w5.66: J2.9@71.48,1738.78 72.07,1738.19 138.65,1738.19 v1(139.25,1737.6) ; v1(1115.71,1519.77) 1092.02,1543.46 1092.02,1844.2 1124.81,1876.99 1124.81,2081.94 1139.08,2096.2 1152.97,2096.2 1171.73,2114.97 1395.87,2114.97 1597.71,2316.81 R98.1@1597.71,2691 SW4.1@1597.71,2788
  SIG1 w6.66: v1(139.25,1737.6) 139.25,1659.44 203.72,1594.96 1040.53,1594.96 v1(1115.71,1519.77) ; v1(993.6,1144.97) 1020.78,1117.8 1189.71,1117.8 1281.99,1210.08 v1(1440.4,1210.08)
  Bottom w5.66: U17.9@983.76,1108 983.76,1135.13 v1(993.6,1144.97) ; U17.10@1003.45,1108 1003.45,1135.13 v1(993.6,1144.97) ; v1(1115.71,1519.77) 1138.23,1519.77 1204,1454 1204,1297.35 1195.55,1288.9 1111.51,1288.9 1095.67,1273.06 1095.67,1241.67 1060.23,1206.23 1001.57,1206.23 993.6,1198.26 v1(993.6,1144.97) ; U18.10@1440.4,1108.29 v1(1440.4,1210.08)
MII_RST#: J3.101 R43.2 U8.1 | length 778.7
  Top Layer w5.66: v1@1899.23,1658.67 1917.74,1640.16 J3.101@1993.48,1640.16 ; v1(2447.72,1642.01) R43.2@2447.72,1616.37 U8.1@2517.35,1616.37
  Bottom w5.66: v1@1899.23,1658.67 1930.68,1690.13 1979.87,1690.13 2027.99,1642.01 v1(2447.72,1642.01)
  other v1: 1899.23,1659.64
MII_RX_ER: J2.15 R66.1 R75.2 R111.1 U2.46 | length 4588.5
  Top Layer w5.66: J2.15@71.48,1679.73 71.84,1680.08 118.25,1680.08 v1(118.61,1680.44) ; R111.1@2809.46,1582.81 2809.46,1658.7 2829,1678.24 2829,1791 2928.89,1890.89 2928.89,2140.28 v1(2983.44,2194.83)
  SIG1 w6.66: v1(118.61,1680.44) 118.61,1960.47 640.13,2481.99 1326,2481.99 1354,2509.99 2855.16,2509.99 2960,2405.15 2960,2218.27 v1(2983.44,2194.83)
  Bottom w5.66: U2.46@2860.39,2112.37 2860.39,2158.72 2877.83,2176.17 2921.44,2176.17 2935.65,2190.38 R75.2@2935.65,2223.58 R66.1@2983.44,2223.58 v1(2983.44,2194.83)
MUX_MDIO0_MDC: R101.1 R159.1 U19.3 | length 1201.4
  Top Layer w5.66: R159.1@296.67,1704.65 296.67,1684.11 312.69,1668.09 312.69,1649.67 v1(314.59,1647.77) ; v1(1161.75,1625.67) 1161.75,1623.18 1207.93,1577 1301,1577 1307.47,1570.53 R101.1@1307.47,1553.49 ; R101.1@1308.69,1552.28 U19.3@1402.41,1552.28
  SIG1 w6.66: v1(314.59,1647.77) 336.7,1625.67 v1(1161.75,1625.67)
MUX_MDIO0_MDIO: R100.1 R162.1 U19.7 | length 2030.6
  Top Layer w5.66: R162.1@296.67,1607.25 335.75,1607.25 374.05,1568.95 374.05,1553.74 v1(376.32,1551.46) ; v1(1197,1510) 1197,1447 1347,1297 1716,1297 1760,1341 1760,1450.99 1742.79,1468.19 1675.97,1468.19 1668.47,1475.69 R100.1@1668.47,1494.49 1667.1,1495.86 1635.66,1495.86 1632.35,1499.18 1632.35,1525.74 1625.49,1532.59 U19.7@1575.63,1532.59
  SIG1 w6.66: v1(376.32,1551.46) 441.92,1485.87 1172.87,1485.87 v1(1197,1510)
NetC88_1: C88.1 U13.2
NetL2_1: L2.1 U10.2 | length 85.4
  Top Layer w7.87: 2779.39,357 2786.98,364.59 ; 2786.98,340.42 2786.98,364.59 ; 2786.98,366.24 2786.98,364.59 ; U10.2@2786.98,413.48 2786.98,364.59
NetR85_2: R85.2 U12.3 | length 66.5
  Top Layer w5.66: R85.2@3093.71,486.45 3094.66,485.49 U12.3@3159.78,485.49
NetR107_1: R107.1 U19.9 | length 115.8
  Top Layer w5.66: U19.9@1575.63,1571.96 1631.46,1571.96 1650.98,1591.48 R107.1@1650.98,1623.81
NetR130_1: R130.1 SW3.2 | length 97
  Top Layer w5.66: R130.1@2304.72,2691 SW3.2@2304.72,2788
NetR131_1: R131.1 SW4.2 | length 97
  Top Layer w5.66: R131.1@1897.71,2691 SW4.2@1897.71,2788
NetR132_1: R132.1 U11.5 | length 75.6
  Top Layer w5.66: U11.5@3530.65,291 3557.76,291 3577.01,271.75 3597.19,271.75 R132.1@3597.94,271
NetR153_1: R153.1 U18.19 | length 218.5
  Bottom w5.66: U18.19@1593.65,1052.88 1641.78,1052.88 1655.13,1066.24 1655.13,1136.87 1627.09,1164.91 R153.1@1627.09,1206.14
OSPI1_RESET_OUT0: R55.2 R122.2 U20.1 | length 2431.2
  Top Layer w5.66: v1(305.16,1176.04) 304.6,1175.48 304.6,762.4 387.1,679.9 R122.2@486.93,679.9 487.23,680.19 487.23,744.13 U20.1@487.49,744.39
  Bottom w5.66: v1(305.16,1176.04) 19.98,1176.04 -1.36,1197.38 -1.36,1480.1 11.6,1493.06 470.97,1493.06 635.34,1657.42 635.34,1701.66 608.96,1728.04 537.18,1728.04 497.76,1767.47 317.69,1767.47 309.54,1775.63 R55.2@309.54,1802.83
PHY0_25MHZ_CLK: J3.117 U1.20 | length 1888.6
  Top Layer w5.66: v1(1918.5,1814.88) 1935.75,1797.64 J3.117@1993.48,1797.64 ; v1(2357.46,1659.84) 2357.46,1583.54 2458.7,1482.3 2458.7,966.65 2400.67,908.62 2400.67,847.71 2410.61,837.77 2453.81,837.77 2473.97,817.61 2722.99,817.61 v1(2761.96,856.58)
  Bottom w5.66: v1(1918.5,1814.88) 1975.56,1814.88 2110.95,1679.49 2337.81,1679.49 v1(2357.46,1659.84) ; v1(2761.96,856.58) U1.20@2761.96,891.89
PHY1_25MHZ_CLK: J3.119 J6.28 | length 963.9
  Top Layer w5.66: v1(1696.06,2246.15) 1696.06,2076.45 1955.18,1817.32 J3.119@1993.48,1817.32
  Bottom w5.66: J6.28@1306.63,2246.15 v1(1696.06,2246.15)
PHY1_CLKOUT: TP10.1 U2.40 | length 188.3
  Bottom w5.66: TP10.1@2722.95,2292.68 2742.28,2273.35 U2.40@2742.28,2112.37
PHY1_MDIO0_MDC: R160.1 U2.42 | length 3252
  Top Layer w5.66: v1@262.68,1795 284.18,1795 296.67,1782.5 R160.1@296.67,1750.66
  SIG1 w6.66: v1(262.68,1794.99) 262.68,2048.77 645.57,2431.67 1217.03,2431.67 1229.09,2443.73 1423.72,2443.73 1445.96,2465.97 2576.6,2465.97 2739.67,2302.9 2739.67,2206.24 2779.44,2166.47 v1(2782.07,2166.47)
  Bottom w5.66: U2.42@2781.65,2112.37 2781.86,2112.58 2781.86,2166.26 v1(2782.07,2166.47)
PHY1_MDIO0_MDIO: R56.2 U2.41 | length 3199.5
  SIG1 w6.66: v1(386.72,1850.07) 321.36,1850.07 276.67,1894.76 276.67,2043.45 651.23,2418.01 1205.8,2418.01 1217.44,2406.36 1406.49,2406.36 1452.44,2452.31 2570.94,2452.31 2725,2298.25 2725,2184.64 v1(2761.96,2147.68)
  Bottom w5.66: R56.2@356.78,1850.07 v1(386.72,1850.07) ; U2.41@2761.96,2112.37 v1(2761.96,2147.68)
PHY1_RBIAS: R58.1 TP9.1 U2.12 | length 179.1
  Bottom w5.66: U2.12@2925.35,1870.24 2949.49,1870.24 2976.54,1843.19 R58.1@3011.87,1843.19 TP9.1@3011.87,1790.19 v1(2983.44,1790.19)
PHY1_RGMII1_RD0: R29.2 R61.1 R70.2 U2.33 | length 3571.3
  SIG1 w6.66: v1(287,1648.71) 307.3,1669.01 321.02,1669.01 346.04,1644 944.04,1644 957.52,1657.48 959.88,1659.83 959.88,1667.37 932.06,1695.19 932.06,1702.73 943.37,1714.04 950.91,1714.04 1014.08,1650.87 1021.62,1650.87 1032.93,1662.18 1032.93,1669.72 969.76,1732.89 969.76,1740.43 981.08,1751.74 988.62,1751.74 1051.79,1688.57 1059.33,1688.57 1070.64,1699.88 1070.64,1707.42 1007.47,1770.59 1007.47,1778.14 1018.78,1789.45 1026.32,1789.45 1089.49,1726.28 1097.03,1726.28 1108.34,1737.59 1108.34,1745.13 1045.17,1808.3 1045.17,1815.84 1056.48,1827.15 1064.02,1827.15 1091.84,1799.33 1099.38,1799.33 1109.02,1808.98 1220.43,1920.38 1575.06,1920.38 1588.77,1906.67 1930.93,1906.67 2007.73,1829.88 2062.39,1829.88 2072.52,1840 2174,1840 v1(2175,1841)
  Bottom w5.66: R29.2@286.78,1607.25 287,1607.47 v1(287,1648.71) ; v1(2175,1841) 2175,2081.3 2214.95,2121.24 2425.55,2121.24 2432.7,2114.09 R61.1@2432.73,2097.11 ; R61.1@2432.73,2097.11 R70.2@2432.73,2048.97 2460.01,2048.97 2468.19,2040.79 2621.65,2040.79 2634.73,2027.72 U2.33@2657.63,2027.72
PHY1_RGMII1_RD1: R32.2 R62.1 R71.2 U2.34 | length 3010.6
  SIG1 w6.66: v1(700,1820) 479.15,1820 458.94,1840.21 458.94,2049.34 633.65,2224.05 1285.48,2224.05 1310.15,2199.38 1684.14,2199.38 1778.6,2293.84 1898.1,2293.84 1910.59,2306.33 2137.32,2306.33 2218.52,2225.13 v1(2432.73,2225.13)
  Bottom w5.66: v1(700,1820) 700,1849.83 R32.2@700.24,1850.07 ; v1(2432.73,2225.13) R71.2@2432.73,2193.38 R62.1@2432.73,2145.38 2455.07,2145.38 2464.11,2136.34 2464.11,2064.05 2473.73,2054.43 2625.92,2054.43 2632.95,2047.41 U2.34@2657.63,2047.41
PHY1_RGMII1_RD2: R34.2 R68.1 R77.2 U2.35 | length 3455
  SIG1 w6.66: v1(401.27,1719.49) 486.78,1719.49 490.11,1719.49 495.44,1724.82 495.44,1755.89 500.78,1761.22 516.77,1761.22 522.1,1755.89 522.1,1724.12 527.44,1718.79 543.43,1718.79 548.76,1724.12 548.76,1755.89 554.1,1761.22 570.09,1761.22 575.42,1755.89 575.42,1724.82 580.76,1719.49 591,1719.49 623.54,1719.49 635,1730.95 635,1789 624,1800 476.28,1800 445.28,1831 445.28,2055 630.15,2239.87 1573.3,2239.87 1663.93,2330.5 2471.47,2330.5 2561.67,2240.3 v1(2561.67,2218)
  Bottom w5.66: R34.2@401.27,1667.25 v1@401.27,1714.82 ; v1(401.27,1719.49) v1@401.27,1714.82 ; 408.45,1710.49 404.12,1714.82 v1@401.27,1714.82 ; v1(2561.67,2218) R77.2@2561.67,2193.38 R68.1@2561.67,2145.38 2561.67,2091.33 2585.91,2067.09 U2.35@2657.63,2067.09
PHY1_RGMII1_RD3: R36.2 R69.1 R78.2 U2.36 | length 3346.5
  SIG1 w6.66: v1(485.5,1701.16) 471.9,1687.56 364.97,1687.56 356.28,1696.25 356.28,1766.57 420.96,1831.25 420.96,1871.11 340.52,1951.56 340.52,2049.34 613.51,2322.33 1097.54,2322.33 ; 1097.56,2322.31 1617.1,2322.31 1675.78,2380.99 2506.01,2380.99 v1(2561,2326)
  Bottom w5.66: v1(485.5,1701.16) 485.5,1607.51 R36.2@485.76,1607.25 ; v1(2561,2326) 2561,2295.36 R69.1@2561.67,2294.69 R78.2@2561.67,2246.69 2587.26,2246.69 2595.26,2238.69 2595.26,2104.87 2613.36,2086.78 U2.36@2657.63,2086.78
PHY1_RGMII1_RST#: R124.2 U2.43 U9.4 | length 942.3
  Top Layer w5.66: U9.4@2050.57,2311.75 R124.2@2108.91,2311.75 2108.91,2275.09 2116,2268 2350.4,2268 2381,2237.4 2381,2165.8 2429.13,2117.67 2771.32,2117.67 v1(2801.33,2147.68)
  Bottom w5.66: U2.43@2801.33,2112.37 v1(2801.33,2147.68)
PHY1_RGMII1_RX_CTL: R27.2 R63.1 R72.2 U2.38 | length 3563.2
  SIG1 w6.66: v1(358.85,2041.75) 358.85,1958.15 376,1941 413,1941 423,1951 423,2017.53 423,2049.72 395.38,2077.34 395.38,2084.88 406.69,2096.19 414.23,2096.19 436.92,2073.5 444.46,2073.5 455.78,2084.81 455.78,2092.35 433.08,2115.05 433.08,2122.59 444.39,2133.9 451.93,2133.9 474.63,2111.2 482.17,2111.2 493.48,2122.51 493.48,2130.05 470.78,2152.75 470.78,2160.29 482.09,2171.6 489.63,2171.6 512.33,2148.91 519.87,2148.91 531.18,2160.22 531.18,2167.76 508.49,2190.45 508.49,2197.99 519.8,2209.3 527.34,2209.3 550.03,2186.61 557.57,2186.61 568.88,2197.92 568.88,2205.46 546.19,2228.15 546.19,2235.69 557.5,2247.01 565.04,2247.01 587.05,2224.99 594.59,2224.99 615.8,2246.2 623.13,2253.53 646,2253.53 649.33,2253.53 654.66,2258.86 654.66,2303.34 659.99,2308.67 675.99,2308.67 681.32,2303.34 681.32,2258.86 686.65,2253.53 702.65,2253.53 707.98,2258.86 707.98,2303.34 713.31,2308.67 729.31,2308.67 734.64,2303.34 734.64,2258.86 739.97,2253.53 755.97,2253.53 761.3,2258.86 761.3,2301.01 766.63,2306.34 782.63,2306.34 787.96,2301.01 787.96,2258.86 793.29,2253.53 807.36,2253.53 1567.64,2253.53 1681.44,2367.33 2453.96,2367.33 2620.97,2200.32 2620.97,2191.99 v1(2623.14,2189.82)
  Bottom w5.66: R27.2@328.91,2041.75 v1(358.85,2041.75) ; v1(2623.14,2189.82) R63.1@2623.14,2223.58 R72.2@2672.24,2223.58 2672.24,2189.08 2702.91,2158.41 U2.38@2702.91,2112.37
PHY1_RGMII1_RXC: R25.2 R59.1 | length 2650.5
  SIG1 w6.66: v1(595.7,2041.75) 561.07,2007.12 561.07,1883.51 549.77,1872.21 484.33,1872.21 473.49,1883.05 473.49,1905.65 473.49,1935.64 478.82,1940.97 501.41,1940.97 506.75,1946.3 506.75,1962.3 501.41,1967.63 478.82,1967.63 473.49,1972.96 473.49,1994 473.49,2008.63 568.08,2103.22 1047.4,2103.22 1085.59,2141.41 1664.81,2141.41 1789.74,2266.35 1918.91,2266.35 1931.56,2279.01 2125.91,2279.01 2320.98,2083.94 2320.98,2026.68 v1(2344,2003.66)
  Bottom w5.66: R25.2@565.76,2041.75 v1(595.7,2041.75) ; v1(2344,2003.66) R59.1@2385.5,2003.66
PHY1_RGMII1_TD0: R48.2 U2.28 | length 3104.4
  SIG1 w6.66: v1(501.21,1850.07) 633.92,1850.07 763.2,1979.36 1150.9,1979.36 1168.9,1961.36 1542.71,1961.36 1559.35,1978 1701.62,1978 1708.31,1984.69 1710.67,1987.04 1710.67,1994.59 1680.57,2024.68 1680.57,2032.22 1691.88,2043.53 1699.42,2043.53 1729.75,2013.2 1737.29,2013.2 1748.61,2024.51 1748.61,2032.05 1718.28,2062.38 1718.28,2069.92 1729.59,2081.23 1737.13,2081.23 1767.46,2050.9 1775,2050.9 1786.31,2062.21 1786.31,2069.75 1755.98,2100.08 1755.98,2107.62 1767.29,2118.93 1774.83,2118.93 1805.16,2088.61 1812.7,2088.61 1824.01,2099.92 1824.01,2107.46 1793.68,2137.79 1793.68,2145.33 1804.99,2156.64 1812.53,2156.64 1842.86,2126.31 1850.4,2126.31 1861.71,2137.62 1861.71,2145.16 1831.39,2175.49 1831.39,2183.03 1842.7,2194.34 1850.24,2194.34 1880.57,2164.01 1888.11,2164.01 1899.42,2175.32 1899.42,2182.86 1881.16,2201.12 1881.16,2208.66 1892.47,2219.97 1900.01,2219.97 1918.03,2201.95 1925.57,2201.95 1957.88,2234.26 1961.65,2238.03 2108.94,2238.03 2279.77,2067.2 2279.77,1980.65 2369.66,1890.76 v1(2384.5,1890.76)
  Bottom w5.66: R48.2@471.27,1850.07 v1(501.21,1850.07) ; v1@2385.5,1890.76 2409.99,1915.25 2625.3,1915.25 2639.35,1929.3 U2.28@2657.63,1929.3
PHY1_RGMII1_TD1: R50.2 U2.27 | length 3312.6
  SIG1 w6.66: v1(240.61,1669.14) 240.61,1738.71 248.98,1747.08 298.12,1747.08 307.3,1737.9 307.3,1702.93 352.28,1657.95 721.86,1657.95 752.05,1688.14 752.05,1948.89 768.86,1965.7 1145.24,1965.7 1163.24,1947.7 1548.37,1947.7 1564.2,1963.54 1707.26,1963.54 1720.27,1976.54 1741.47,1997.75 1749.02,1997.75 1762.9,1983.87 1770.44,1983.87 1781.75,1995.18 1781.75,2002.72 1767.53,2016.94 1767.53,2024.48 1778.84,2035.79 1786.38,2035.79 1800.6,2021.57 1808.14,2021.57 1819.45,2032.88 1819.45,2040.42 1805.57,2054.31 1805.57,2061.85 1864.36,2120.64 1968.09,2224.37 2103.28,2224.37 2266.11,2061.54 2266.11,1973.15 v1(2384.5,1854.76)
  Bottom w5.66: R50.2@202.29,1667.25 204.18,1669.14 v1(240.61,1669.14) ; v1@2385.5,1854.76 2433.33,1902.59 2632.4,1902.59 2639.43,1909.61 U2.27@2657.63,1909.61
PHY1_RGMII1_TD2: R52.2 U2.26 | length 2974.5
  SIG1 w6.66: v1(477.27,2041.75) 586.52,2151 827.04,2151 832.37,2156.33 832.37,2197.21 837.7,2202.54 853.7,2202.54 859.03,2197.21 859.03,2156.33 864.36,2151 880.36,2151 885.69,2156.33 885.69,2197.21 891.02,2202.54 907.02,2202.54 912.35,2197.21 912.35,2156.33 917.68,2151 933.68,2151 939.01,2156.33 939.01,2196.21 944.34,2201.54 960.34,2201.54 965.67,2196.21 965.67,2156.33 971,2151 1009.62,2151 1069,2210.39 1279.82,2210.39 1304.49,2185.72 1689.79,2185.72 1784.25,2280.18 1903.76,2280.18 1916.24,2292.67 2131.67,2292.67 2254.16,2170.17 2403.36,2170.17 2421.5,2152.04 v1(2421.5,1854.76)
  Bottom w5.66: R52.2@447.33,2041.75 v1(477.27,2041.75) ; v1(2421.5,1854.76) 2456.67,1889.93 U2.26@2657.63,1889.93
PHY1_RGMII1_TD3: R54.2 U2.25 | length 2639.3
  SIG1 w6.66: v1(710.18,2041.75) 804.3,2041.75 807.63,2041.75 812.97,2047.08 812.97,2077.55 818.3,2082.89 834.29,2082.89 839.63,2077.55 839.63,2040.68 844.96,2035.35 860.95,2035.35 866.29,2040.68 866.29,2077.55 871.62,2082.89 887.61,2082.89 892.95,2077.55 892.95,2040.68 898.28,2035.35 914.27,2035.35 919.61,2040.68 919.61,2077.55 924.94,2082.89 940.93,2082.89 946.27,2077.55 946.27,2047.08 951.6,2041.75 1010.25,2041.75 1034.12,2041.75 1088.86,2096.48 1153.25,2096.48 1163.76,2107 1402.24,2107 1424.9,2084.34 1627.05,2084.34 1795.4,2252.69 1924.57,2252.69 1937.22,2265.35 2120.25,2265.35 2307.09,2078.51 2307.09,2011.18 2340.46,1977.81 2355.3,1977.81 2402.83,1930.28 2402.83,1830.26 2410.27,1822.81 2450.49,1822.81 2457.5,1829.82 v1(2457.5,1854.76)
  Bottom w5.66: R54.2@680.24,2041.75 v1(710.18,2041.75) ; v1(2457.5,1854.76) 2472.98,1870.24 U2.25@2657.63,1870.24
PHY1_RGMII1_TX_CTL: R46.2 U2.37 | length 3481.1
  SIG1 w6.66: v1(600.24,1697.19) 575.63,1672.58 359.29,1672.58 340.2,1691.67 340.2,1771.35 407.3,1838.45 407.3,1864.6 326.86,1945.05 326.86,2055 662.55,2390.69 1194.48,2390.69 1206.13,2379.04 1417.81,2379.04 1463.76,2424.99 1799.45,2424.99 1829.79,2394.65 2571.35,2394.65 2649.14,2316.86 v1(2649.14,2189.78)
  Bottom w5.66: R46.2@600.24,1667.25 v1(600.24,1697.19) ; v1(2649.14,2189.78) 2683.22,2155.7 U2.37@2683.22,2112.37
PHY1_RGMII1_TXC: R38.2 R57.1 | length 2861.8
  SIG1 w6.66: v1(586.74,1883.33) 586.74,1995.15 589.94,1998.35 593.62,2002.03 619.93,2002.03 625.26,1996.7 625.26,1931.58 630.6,1926.25 646.59,1926.25 651.92,1931.58 651.92,2000.11 657.26,2005.44 673.25,2005.44 678.58,2000.11 678.58,1954.24 683.92,1948.91 699.91,1948.91 705.24,1954.24 705.24,1996.7 710.58,2002.03 744.22,2002.03 1628.49,2002.03 1650.13,2023.67 1652.48,2026.03 1652.48,2033.57 1627.81,2058.24 1627.81,2065.78 1639.12,2077.09 1646.66,2077.09 1672.62,2051.13 1680.17,2051.13 1691.48,2062.44 1691.48,2069.98 1665.51,2095.94 1665.51,2103.48 1676.82,2114.79 1684.36,2114.79 1710.33,2088.83 1717.87,2088.83 1729.18,2100.14 1729.18,2107.68 1703.22,2133.65 1703.22,2141.19 1714.53,2152.5 1722.07,2152.5 1748.03,2126.53 1755.57,2126.53 1766.88,2137.84 1766.88,2145.39 1740.92,2171.35 1740.92,2178.89 1752.23,2190.2 1759.77,2190.2 1785.73,2164.24 1793.27,2164.24 1804.59,2175.55 1804.59,2183.09 1778.62,2209.05 1778.62,2216.59 1789.93,2227.9 1797.47,2227.9 1822.15,2203.23 1829.69,2203.23 1865.49,2239.03 1873.97,2239.03 1930.22,2239.03 1942.88,2251.69 2114.6,2251.69 2293.43,2072.86 2293.43,2003.93 v1(2344,1953.35)
  Bottom w5.66: R38.2@585.76,1850.07 586.74,1851.06 v1(586.74,1883.33) ; v1(2344,1953.35) R57.1@2385.5,1953.35
PHY2_CLKOUT: TP7.1 U1.40 | length 188.3
  Bottom w5.66: TP7.1@2722.95,1339.92 2742.28,1320.59 U1.40@2742.28,1159.61
PHY2_RBIAS: R2.1 TP6.1 U1.12 | length 150.7
  Bottom w5.66: U1.12@2925.35,917.48 2949.49,917.48 2976.54,890.44 R2.1@3011.87,890.44 TP6.1@3011.87,837.44
PMIC_COMP1_IN+: EC2.175 J3.37 | length 3394.5
  Top Layer w4: v1(1908.48,830.6) 1907,829.12 1907,817 1914.96,809.04 1959.62,809.04 1959.96,809.38 1989.48,809.38 J3.37@1993.48,813.39 ; EC2.175@3631.02,-522.97 3631.02,-478.68 3641.27,-468.43 3641.27,-461.48 3631.05,-451.26 3631.05,-259.3 3750.95,-139.41 3750.95,521.92 3666.5,606.37 3666.5,636.52 v1(3650.85,652.17)
  Bottom w4: v1(1908.48,830.6) 1910.19,828.89 1910.19,812.05 1996.45,725.79 1996.45,615.26 2018.22,593.49 2426.94,593.49 2498.41,664.97 2824.04,664.97 2868.83,620.17 3659.18,620.17 3666.5,627.49 3666.5,637.85 3652.18,652.17 v1(3650.85,652.17)
PMIC_COMP1_IN-: EC2.177 J3.35 | length 3432.3
  Top Layer w4: v1(1884.44,808.93) 1884.73,809.22 1899.22,809.22 1910.4,798.04 1959.62,798.04 1959.96,797.71 1989.48,797.71 J3.35@1993.48,793.7 ; EC2.177@3662.52,-522.97 3662.52,-478.68 3652.27,-468.43 3652.27,-456.92 3642.05,-446.7 3642.05,-263.86 3761.95,-143.96 3761.95,526.48 3677.5,610.93 3677.5,636.52 v1(3693.15,652.17)
  Bottom w4: v1(1884.44,808.93) 1887.11,806.25 1900.43,806.25 1985.45,721.24 1985.45,610.71 1991.89,604.26 2007.22,588.94 2013.66,582.49 2431.49,582.49 2502.97,653.97 2819.48,653.97 2864.28,609.17 3663.73,609.17 3677.5,622.94 3677.5,637.85 3691.82,652.17 v1(3693.15,652.17)
PMIC_COMP2_IN+: EC2.171 J3.33 | length 3517
  Top Layer w4: v1(1817.62,830.04) 1816.14,828.56 1816.14,816.44 1862.9,769.67 1959.62,769.67 1959.96,770.01 1989.48,770.01 J3.33@1993.48,774.02 ; EC2.171@3568.03,-522.97 3576.86,-514.14 3576.86,-463.95 3578.28,-462.53 3578.28,-241.14 3698.81,-120.62 3698.81,504.67 3667.17,536.31 3631.54,536.31 3620.5,525.27 3620.5,507.32 3632,495.82 v1(3632,493)
  Bottom w4: v1(1817.62,830.04) 1819.62,828.04 1819.62,811.78 1953.92,677.47 1953.92,606.87 2003.3,557.49 2444.39,557.49 2515.86,628.97 2809.13,628.97 2876.55,561.54 3606.73,561.54 3620.5,547.78 3620.5,507.32 3632,495.82 v1(3632,493)
PMIC_COMP2_IN-: EC2.173 J3.31 | length 3555.1
  Top Layer w4: v1(1793.58,808.37) 1793.87,808.66 1808.36,808.66 1858.35,758.67 1959.62,758.67 1959.96,758.34 1989.48,758.34 J3.31@1993.48,754.33 ; v1(3598,493) 3598,495.82 3609.5,507.32 3609.5,529.83 3626.98,547.31 3671.72,547.31 3709.81,509.23 3709.81,472.27 3709.81,-125.17 3703.37,-131.62 3589.28,-245.7 3589.28,-462.53 3590.7,-463.95 3590.7,-514.14 EC2.173@3599.53,-522.97
  Bottom w4: v1(1793.58,808.37) 1797.37,808.37 1801.73,804 1811.84,804 1942.92,672.91 1942.92,602.32 1949.37,595.87 1992.3,552.94 1998.75,546.49 2448.94,546.49 2452.16,549.72 2509.71,607.26 2520.42,617.97 2804.57,617.97 2865.55,556.99 2871.99,550.54 3602.18,550.54 3609.5,543.22 3609.5,507.32 3598,495.82 v1(3598,493)
PMIC_SAFE_OUT1: EC2.178 J1.32 | length 2837.5
  Top Layer w5.66: v1(1418.8,401.47) J1.32@1418.84,444.88
  SIG1 w6.66: v1(1418.8,401.47) 1420.97,399.3 1420.97,386.09 1437.97,369.1 1440.63,369.1 1637.27,172.46 1731.51,172.46 1760.75,143.22 2206.47,143.22 2229.12,120.57 2864.7,120.57 3091.57,-106.3 3476.3,-106.3 v1(3566,-196)
  Bottom w5.66: v1(3566,-196) 3566,-405 3606.67,-445.67 3648.79,-445.67 3662.52,-459.39 EC2.178@3662.52,-522.97
PMIC_SAFE_OUT2: EC1.113 J3.29 | length 1406.5
  Top Layer w5.66: EC1.113@1861.68,-528.32 1861.68,-463.68 1872,-453.36 1872,-418 1795.97,-341.97 1795.97,80.75 1848.42,133.21 1848.42,470.21 1943.57,565.36 1943.57,728.99 1949.23,734.65 J3.29@1993.48,734.65
PMIC_WAKE2: EC1.114 J1.30 | length 1530.7
  Top Layer w5.66: J1.30@1438.52,444.88 1438.52,409.18 1444.88,402.82 v1(1444.88,388.11)
  SIG1 w6.66: v1(1444.88,388.11) 1502.79,330.2 1502.79,326.26 1642.93,186.12 1737.16,186.12 1760.96,162.33 v1(2032.72,162.33)
  Bottom w5.66: EC1.114@1861.68,-528.32 1861.68,-463.68 1874.18,-451.18 1918.82,-451.18 1942.74,-427.26 1942.74,-340.14 1982.63,-300.25 1982.63,-132.51 2032.72,-82.42 v1(2032.72,162.33)
PR0_MDIO0_MDC: EC1.90 J3.97 J6.20 R103.1 U19.2 | length 4556
  Top Layer w5.66: U19.2@1402.41,1571.96 1360.57,1571.96 1328.54,1603.99 R103.1@1307.47,1603.99 1307.73,1604.26 1307.73,1624.53 1297.27,1635 1223.58,1635 1212.78,1645.8 1212.78,1678.07 1223.61,1688.9 1268.97,1688.9 1322.07,1742 1698.73,1742 ; v1(1569.47,2105.47) 1743.73,1931.21 1743.73,1787 1698.73,1742 ; J3.97@1993.48,1600.79 1904.23,1600.79 1878.15,1574.7 1843.29,1574.7 1814.85,1546.26 1764.37,1546.26 1743.73,1566.9 1743.73,1697 1698.73,1742
  Bottom w5.66: J6.20@1306.63,2183.16 1368.34,2183.16 1376.17,2175.33 1499.62,2175.33 v1(1569.47,2105.47) ; EC1.90@1483.72,-528.32 1483.72,-484.03 1491.72,-476.04 1492.25,-476.04 1495.56,-472.72 1495.56,-435.52 1526.61,-404.48 1528.04,-404.48 1559.08,-373.44 1643.56,-373.44 1726.32,-290.68 1726.32,-183.51 1859.93,-49.9 1859.93,32.76 1930.88,103.7 1930.88,320.13 1836.57,414.43 1734,414.43 1626.13,522.31 1626.13,766.28 1733.66,873.82 1733.66,1195.14 1752.35,1213.83 1752.35,1533.54 1763.08,1544.27 v1@1763.08,1547.55
  other v1: 1763.17,1547.55
PR0_MDIO0_MDC_ON: R104.1 U1.42 U19.4 | length 1856
  Top Layer w5.66: U19.4@1402.41,1532.59 1355.4,1532.59 1332.99,1510.19 R104.1@1307.47,1510.19 1307.47,1386.91 1363.97,1330.41 v1(1422.89,1330.41)
  SIG1 w6.66: v1(1422.89,1330.41) 1434.4,1341.92 1675.48,1341.92 1692.34,1325.06 1813.71,1325.06 1836.71,1348.06 2340.94,1348.06 2376.92,1312.08 2682.96,1312.08 v1(2781.72,1213.32)
  Bottom w5.66: U1.42@2781.68,1159.65 v1@2781.68,1213.29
